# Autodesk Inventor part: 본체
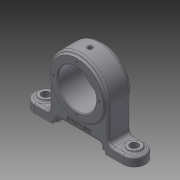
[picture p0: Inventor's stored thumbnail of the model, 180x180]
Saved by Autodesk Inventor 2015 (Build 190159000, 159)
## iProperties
Created: 2019-05
Part Number: 본체
Material: 알루미늄 6061
Document SubType Name: Modeling
Designer: 10403
Density: 2.7 g/cm^3
Appearance: 기본값
Mass: 454.389 g
Surface Area: 318.676 cm^2
Volume: 168.292 cm^3
Author: 10403
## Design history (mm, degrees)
sketch "스케치1"
  geometry: C1 r 40 at (0, 0); 1 further point
  constraints: 1 centre point, 1 coincident
  dimensions: "d0" = 80 diameter of C1
extrude "돌출1" new body sketch "스케치1" stored distance "d1" = 36; taper "d2" = 0 deg
sketch "스케치2"
  geometry: C1 r 40 at (0, 0) reference; C2 r 36 at (0, 0)
  constraints: 1 centre point, 1 coincident
  dimensions: "d3" = 72 diameter of C2
extrude "돌출2" cut sketch "스케치2" distance "d4" = 3; taper "d5" = 0 deg
sketch "스케치3"
  geometry: C1 r 36 at (0, 0) reference
hole "구멍1" sketch "스케치3" at (0, 0) diameter "d6" = 52; stored, may be unused: countersink angle "d10" = 90 deg, drill point angle "d12" = 118 deg; dims "d7" = 6, "d8" = 4, "d9" = 2, "d11" = 8
sketch "스케치4"
  geometry: L1 (75, -48)-(-75, -48); L2 (-75, -48)-(-75, -60); L3 (-75, -60)-(75, -60); L4 (75, -60)-(75, -48); C1 r 26 at (0, 0) reference; C2 r 40 at (0, 0) reference; 2 further points
  constraints: 8 end point, 2 parallel, 1 horizontal, 1 midpoint, 1 perpendicular, 1 vertical alignment
  dimensions: "d13" = 150 distance of L2.end L3.end; "d14" = 12 distance between parallel lines of L1 L3; "d15" = 60 distance from line of L3 point (0, 0)
extrude "돌출3" join sketch "스케치4" stored distance "d16" = 30; taper "d17" = 0 deg
fillet "모깎기1" dims "d18" = 15
sketch "스케치5"
  geometry: C1 r 9 at (0, -15); A1 r 15 centre (0, -15) between (0, 0) and (0, -30) reference; 1 further point
  constraints: 1 centre point, 1 coincident
  dimensions: "d19" = 18 diameter of C1
extrude "돌출4" join sketch "스케치5" distance "d20" = 3; taper "d21" = 0 deg
sketch "스케치6"
  geometry: C1 r 9 at (0, 0) reference; 1 further point
hole "구멍2" sketch "스케치6" at (0, 0) diameter "d22" = 11; stored, may be unused: countersink angle "d26" = 90 deg, drill point angle "d28" = 118 deg; dims "d23" = 6, "d24" = 4, "d25" = 2, "d27" = 8
sketch "스케치7"
  geometry: L1 (0, 0)-(120, 0) reference; L2 (20, -30)-(100, -30); L3 (100, -30)-(100, 0); L4 (100, 0)-(20, 0); L5 (20, 0)-(20, -30); L6 (20, -30)-(100, 0); L7 (100, -30)-(20, 0); 1 further point
  constraints: 12 end point, 2 midpoint, 2 parallel, 1 horizontal, 1 perpendicular, 1 point on line
  dimensions: "d29" = 40 distance from line of point (60, -15) L5
extrude "돌출5" join sketch "스케치7" stored distance "d30" = 3; taper "d31" = 0 deg
sketch "스케치8"
  geometry: L1 (-60, -60)-(60, -60) reference; L2 (-36, -56)-(36, -56); L3 (36, -56)-(36, -60); L4 (36, -60)-(-36, -60); L5 (-36, -60)-(-36, -56); 1 further point
  constraints: 8 end point, 2 midpoint, 2 parallel, 1 horizontal, 1 perpendicular
  dimensions: "d32" = 72 distance of L2.start L2.end; "d33" = 4 distance between parallel lines of L2 L1
extrude "돌출6" cut sketch "스케치8" stored distance "d34" = 3; taper "d35" = 0 deg
sketch "스케치9"
  geometry: L1 (-36, -56)-(36, -56) reference; L2 (-30, -50)-(30, -50); L3 (30, -50)-(30, -56); L4 (30, -56)-(-30, -56); L5 (-30, -56)-(-30, -50); 1 further point
  constraints: 8 end point, 2 midpoint, 2 parallel, 1 horizontal, 1 perpendicular
  dimensions: "d36" = 60 distance of L2.start L2.end; "d37" = 6 distance between parallel lines of L4 L2
extrude "돌출7" cut sketch "스케치9" stored distance "d38" = 3; taper "d39" = 0 deg
sketch "스케치10"
  geometry: C1 r 26 at (0, 0) reference; 1 further point
  constraints: 1 vertical alignment
  dimensions: "d40" = 31 distance of C1.centre point (0, 31)
hole "구멍3" sketch "스케치10" at (0, 31) diameter "d41" = 3.242; stored, may be unused: countersink angle "d45" = 90 deg, drill point angle "d47" = 118 deg; dims "d42" = 6, "d43" = 4, "d44" = 2, "d46" = 8
node "작업 평면1"
sketch "스케치11"
  geometry: 1 further point
hole "구멍4" sketch "스케치11" at (60, 0) diameter "d52" = 4.917; stored, may be unused: countersink angle "d56" = 90 deg, drill point angle "d58" = 118 deg; dims "d53" = 8, "d54" = 7, "d55" = 1, "d57" = 10
sketch "스케치12"
  geometry: C1 r 1 at (60, 0); 1 further point
  constraints: 1 centre point, 1 coincident
  dimensions: "d59" = 2 diameter of C1
extrude "돌출8" cut sketch "스케치12" distance "d60" = 40; taper "d61" = 0 deg
sketch "스케치13"
  geometry: L1 (-30, -50)-(30, -50) reference; A1 r 40 centre (0, 0) between (40, 0) and (-40, 0) reference; 1 further point
  constraints: 1 vertical alignment, 1 other
  dimensions: "d62" = 7 distance from line of point (0, -43) L1
feature "엠보싱1" sketch "스케치13" dims "d13" = 150, "d14" = 12, "d15" = 60, "d63" = 0.5, "d64" = 0
fillet "모깎기2" dims "d65" = 3
fillet "모깎기3" dims "d66" = 3
fillet "모깎기4" dims "d67" = 6
fillet "모깎기5" dims "d68" = 3
fillet "모깎기6" dims "d69" = 3
fillet "모깎기7" dims "d70" = 3
fillet "모깎기8" dims "d71" = 3
chamfer "모따기1" distance "d72" = 1; stored, may be unused: second distance "d73" = 2, angle "d74" = 45 deg
sketch "스케치14"
  geometry: C1 r 1.5 at (0, 26); A1 r 36 centre (0, 0) between (34.154, -11.38) and (-34.154, -11.38) reference; 2 further points
  constraints: 3 vertical alignment, 1 centre point, 2 other
  dimensions: "d75" = 3 diameter of C1
extrude "돌출9" cut sketch "스케치14" stored distance "d76" = 10; taper "d77" = 0 deg
node "솔리드1"
mirror "대칭1"
mirror "대칭2"
pattern_circular "원형 패턴1" dims angle "d49" = 360 deg
mirror "대칭3"
node "절단 모서리 투영1"
